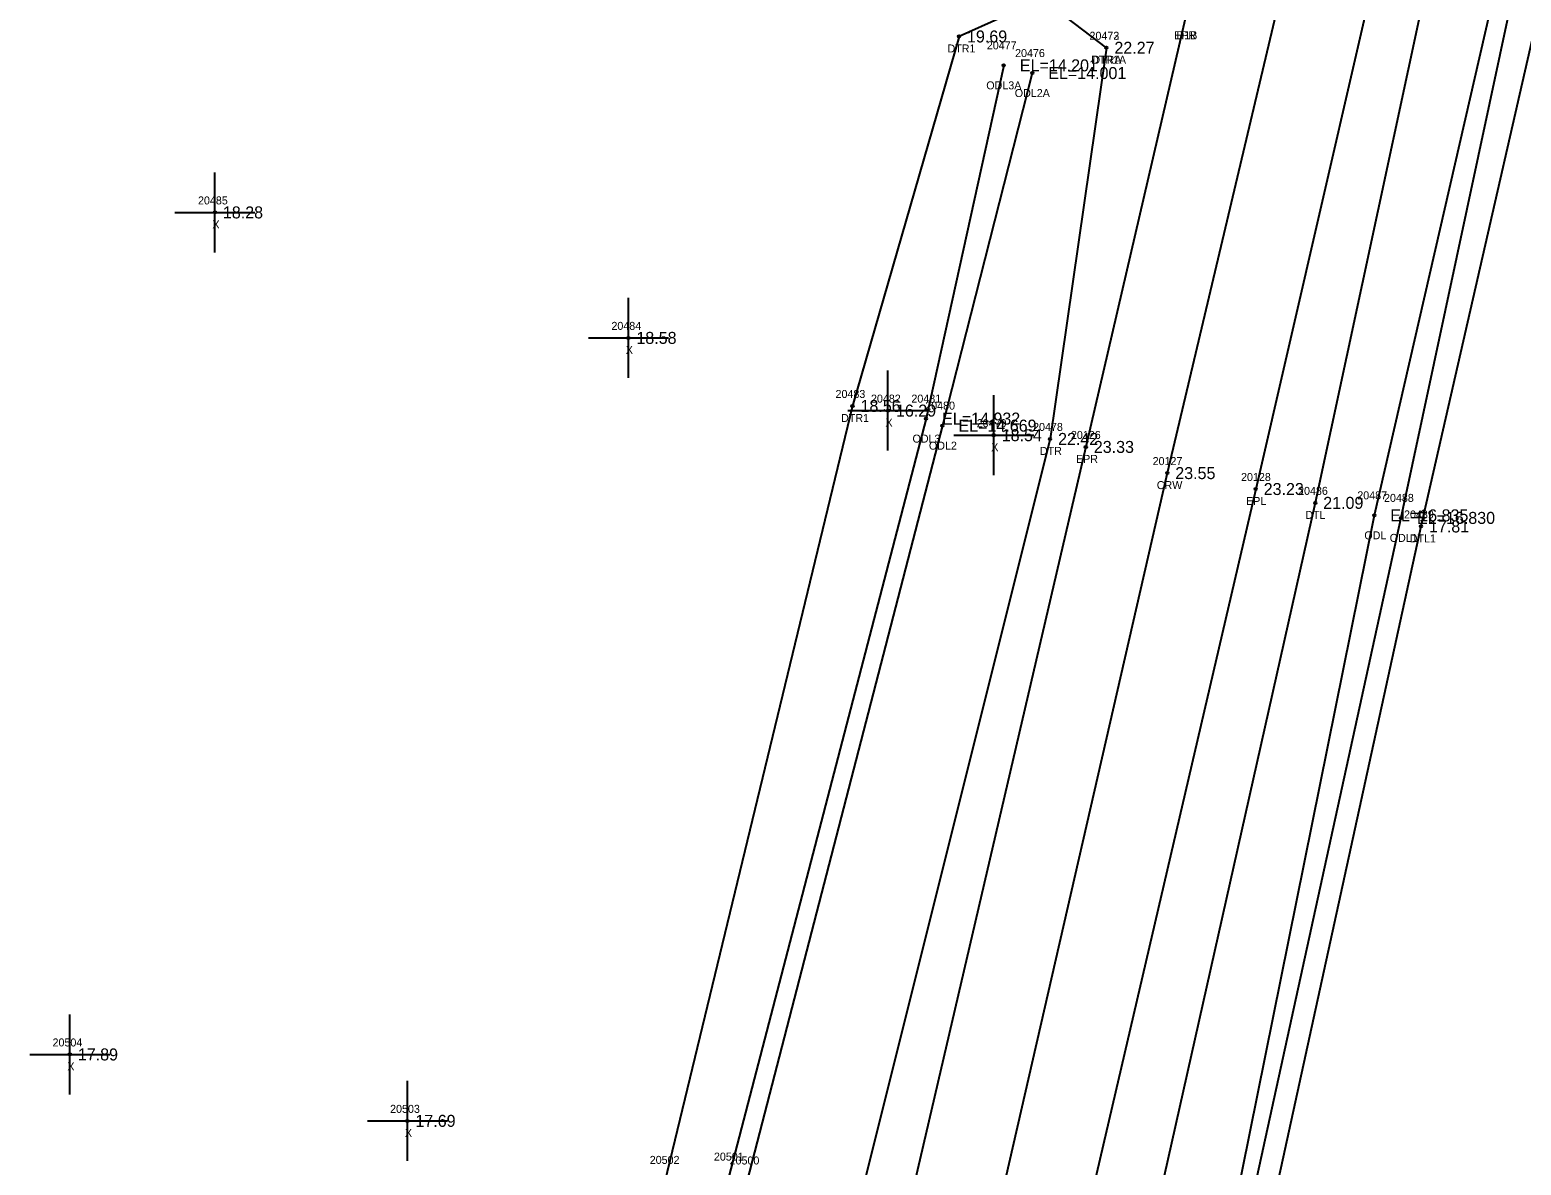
# Model space of a CAD drawing. Extents: x 2655177 to 2656219, y 761780 to 764748.
# Drawn here: x 2655627.1 to 2655813.5, y 763397.1 to 763539 of the extents above; entities that cross this region are included whole.
import ezdxf

# ---------------------------------------------------------------- set-up
doc = ezdxf.new("R2010")
doc.units = 0
for name, color, linetype in [('RD_DTM_BkLn1', 7, 'Continuous'), ('RD_EX_Driveway_txCode', 7, 'Continuous'), ('RD_EX_H2O', 7, 'Continuous'), ('RD_EX_H2O_txCode', 7, 'Continuous'), ('RD_EX_Misc', 7, 'Continuous'), ('RD_EX_Misc_txCode', 7, 'Continuous'), ('RD_EX_Road', 7, 'Continuous'), ('RD_EX_Road_txCode', 7, 'Continuous'), ('RD_EX_TX_H2O_ELEV', 7, 'Continuous'), ('RD_EX_TX_Misc_ELEV', 7, 'Continuous'), ('RD_EX_TX_Road_ELEV', 7, 'Continuous'), ('RD_HC_Survey_ELEV', 7, 'Continuous'), ('RD_HC_Survey_txCode', 7, 'Continuous'), ('RD_SMD_Locator', 7, 'Continuous')]:
    doc.layers.add(name, color=color, linetype=linetype)

msp = doc.modelspace()

# ---------------------------------------------------------------- linework, layer by layer
at = {"layer": 'RD_DTM_BkLn1'}
msp.add_lwpolyline([(2656052.36, 764720.46), (2656029.22, 764619.66), (2656007.41, 764523.97), (2655985.61, 764427.64), (2655963.53, 764330.64), (2655941.2, 764233.56), (2655920.06, 764141.06), (2655898.52, 764047.86), (2655877.71, 763954.88), (2655855.89, 763859.81), (2655834.07, 763763.97), (2655811.81, 763666.79), (2655790.48, 763573.22), (2655769.27, 763483.63), (2655747.64, 763389.32), (2655725.4, 763293.96), (2655721.51, 763275.9)], dxfattribs=at)
at = {"layer": 'RD_EX_H2O'}
for points in [[(2655866.2, 763781.92), (2655858.43, 763782.12), (2655853.29, 763757.63), (2655831.21, 763662.14), (2655807.21, 763570.59), (2655787.76, 763479.91), (2655766.41, 763384.86), (2655751.38, 763287.62), (2655745.55, 763261.6)], [(2655866.2, 763781.92), (2655866.81, 763773.88), (2655862.68, 763756.12), (2655841.51, 763659.39), (2655821.68, 763567.67), (2655800.98, 763476.96), (2655780.09, 763381.34), (2655766.41, 763289.68), (2655763.83, 763255.61)], [(2655859.17, 763772.66), (2655856.61, 763756.77), (2655834.86, 763661.01), (2655815.86, 763568.74), (2655795.14, 763478.35), (2655775.69, 763381.88), (2655758.88, 763290.93), (2655758.58, 763269.84), (2655756.39, 763249.8)], [(2655862.03, 763772.5), (2655859.51, 763756.17), (2655837.49, 763660.31), (2655817.79, 763568.47), (2655798.48, 763478.03), (2655777.42, 763381.75), (2655761.98, 763290.17), (2655758.58, 763269.84)], [(2655761.66, 763536.79), (2655753.68, 763542.9), (2655743.24, 763538.2), (2655729.93, 763492.02), (2655706.75, 763396.29), (2655684.97, 763303.64), (2655679.52, 763275.1)], [(2655761.66, 763536.79), (2655754.62, 763487.9), (2655730.78, 763392.48), (2655710.33, 763297.53), (2655707.49, 763283.28), (2655700.44, 763271.88)], [(2655748.84, 763534.59), (2655739.13, 763490.44), (2655714.48, 763395.7), (2655693.36, 763300.15), (2655683.42, 763267.23)], [(2655752.39, 763533.63), (2655741.17, 763489.56), (2655716.77, 763395.22), (2655694.81, 763299.79), (2655684.92, 763267.82)]]:
    msp.add_lwpolyline(points, dxfattribs=at)
at = {"layer": 'RD_EX_Misc'}
for p, q in [((2655650.24, 763511.21), (2655650.24, 763521.21)), ((2655645.24, 763516.21), (2655655.24, 763516.21)), ((2655701.92, 763495.53), (2655701.92, 763505.53)), ((2655696.92, 763500.53), (2655706.92, 763500.53)), ((2655734.36, 763486.44), (2655734.36, 763496.44)), ((2655747.58, 763483.37), (2655747.58, 763493.37)), ((2655729.36, 763491.44), (2655739.36, 763491.44)), ((2655742.58, 763488.37), (2655752.58, 763488.37)), ((2655632.11, 763405.97), (2655632.11, 763415.97)), ((2655627.11, 763410.97), (2655637.11, 763410.97)), ((2655674.3, 763397.67), (2655674.3, 763407.67)), ((2655669.3, 763402.67), (2655679.3, 763402.67))]:
    msp.add_line(p, q, dxfattribs=at)
at = {"layer": 'RD_EX_Road'}
for points in [[(2656041.72, 764723.31), (2656018.5, 764622.03), (2656002.75, 764552.49), (2655997.43, 764530.02), (2655974.74, 764429.64), (2655952.97, 764333.57), (2655930.52, 764235.7), (2655909.18, 764142.93), (2655887.93, 764050.57), (2655866.91, 763957.26), (2655846.82, 763869.53), (2655845.21, 763862.22), (2655839.99, 763839.71), (2655823.38, 763766.66), (2655801.33, 763669.93), (2655780.03, 763576.53), (2655774.26, 763551.85), (2655771.37, 763539.86), (2655759.09, 763486.9), (2655736.94, 763391.72), (2655715.19, 763296.77), (2655711.35, 763278.45)], [(2655930.84, 764138.62), (2655926.81, 764121.01), (2655909.26, 764045.26), (2655908.15, 764039.87), (2655902.08, 764013.51), (2655888.19, 763952.26), (2655880.73, 763919.6), (2655875, 763893.73), (2655866.73, 763857), (2655852.89, 763796.34), (2655850.73, 763786.52), (2655844.88, 763760.97), (2655822.62, 763664.7), (2655801.12, 763571.82), (2655780.32, 763481.64), (2655758.16, 763386.38), (2655736.73, 763291.27), (2655733.33, 763273.46)]]:
    msp.add_lwpolyline(points, dxfattribs=at)
at = {"layer": 'RD_SMD_Locator'}
for centre in [(2655743.24, 763538.2), (2655761.66, 763536.79), (2655761.66, 763536.79), (2655748.84, 763534.59), (2655752.39, 763533.63), (2655650.24, 763516.21), (2655701.92, 763500.53), (2655729.93, 763492.02), (2655734.36, 763491.44), (2655739.13, 763490.44), (2655741.17, 763489.56), (2655747.58, 763488.37), (2655754.62, 763487.9), (2655759.09, 763486.9), (2655769.27, 763483.63), (2655780.32, 763481.64), (2655787.76, 763479.91), (2655795.14, 763478.35), (2655798.48, 763478.03), (2655800.98, 763476.96), (2655632.11, 763410.97), (2655674.3, 763402.67)]:
    msp.add_circle(centre, 0.15, dxfattribs=at)

# ---------------------------------------------------------------- texts
at = {"layer": 'RD_EX_Driveway_txCode'}
msp.add_text('D1B', height=1, dxfattribs=at).set_placement((2655770.43, 763537.86))
at = {"layer": 'RD_EX_H2O_txCode'}
for s, p in [('DTR1', (2655741.8, 763536.2)), ('20477', (2655746.72, 763536.59)), ('20472', (2655759.55, 763537.79)), ('20473', (2655759.55, 763537.79)), ('20476', (2655750.25, 763535.63)), ('DTR1A', (2655759.74, 763534.79)), ('DTRA', (2655759.91, 763534.79)), ('ODL3A', (2655746.65, 763531.59)), ('ODL2A', (2655750.21, 763530.63)), ('20483', (2655727.81, 763493.02)), ('20481', (2655737.29, 763492.44)), ('20480', (2655739.02, 763491.56)), ('DTR1', (2655728.5, 763490.02)), ('20478', (2655752.5, 763488.9)), ('ODL3', (2655737.43, 763487.44)), ('ODL2', (2655739.48, 763486.56)), ('DTR', (2655753.35, 763485.9)), ('20486', (2655785.62, 763480.91)), ('20487', (2655793.02, 763480.35)), ('20488', (2655796.36, 763480.03)), ('DTL', (2655786.52, 763477.91)), ('20489', (2655798.86, 763477.96)), ('ODL', (2655793.9, 763475.35)), ('ODL1', (2655797.07, 763475.03)), ('DTL1', (2655799.57, 763474.96)), ('20502', (2655704.59, 763397.29)), ('20501', (2655712.61, 763397.7)), ('20500', (2655714.57, 763397.22))]:
    msp.add_text(s, height=1, dxfattribs=at).set_placement(p)
at = {"layer": 'RD_EX_Misc_txCode'}
for s, p in [('20485', (2655648.13, 763517.21)), ('X', (2655649.93, 763514.21)), ('20484', (2655699.8, 763501.53)), ('X', (2655701.6, 763498.53)), ('20482', (2655732.24, 763492.44)), ('X', (2655734.05, 763489.44)), ('20479', (2655745.46, 763489.37)), ('X', (2655747.27, 763486.37)), ('20504', (2655629.95, 763411.97)), ('X', (2655631.8, 763408.97)), ('20503', (2655672.14, 763403.67)), ('X', (2655673.99, 763400.67))]:
    msp.add_text(s, height=1, dxfattribs=at).set_placement(p)
at = {"layer": 'RD_EX_Road_txCode'}
for s, p in [('EPR', (2655770.14, 763537.86)), ('20126', (2655757.23, 763487.9)), ('EPR', (2655757.86, 763484.9)), ('20128', (2655778.49, 763482.64)), ('EPL', (2655779.12, 763479.64))]:
    msp.add_text(s, height=1, dxfattribs=at).set_placement(p)
at = {"layer": 'RD_EX_TX_H2O_ELEV'}
for s, p in [('19.69', (2655744.24, 763537.45)), ('22.27', (2655762.66, 763536.04)), ('22.27', (2655762.66, 763536.04)), ('EL=14.201', (2655750.84, 763533.84)), ('EL=14.001', (2655754.39, 763532.88)), ('18.56', (2655730.93, 763491.27)), ('EL=14.932', (2655741.13, 763489.69)), ('EL=14.669', (2655743.17, 763488.81)), ('22.42', (2655755.62, 763487.15)), ('21.09', (2655788.76, 763479.16)), ('EL=16.835', (2655797.14, 763477.6)), ('EL=16.830', (2655800.48, 763477.28)), ('17.81', (2655801.98, 763476.21))]:
    msp.add_text(s, height=1.5, dxfattribs=at).set_placement(p)
at = {"layer": 'RD_EX_TX_Misc_ELEV'}
for s, p in [('18.28', (2655651.24, 763515.46)), ('18.58', (2655702.92, 763499.78)), ('16.29', (2655735.36, 763490.69)), ('18.54', (2655748.58, 763487.62)), ('17.89', (2655633.11, 763410.22)), ('17.69', (2655675.3, 763401.92))]:
    msp.add_text(s, height=1.5, dxfattribs=at).set_placement(p)
at = {"layer": 'RD_EX_TX_Road_ELEV'}
for s, p in [('23.33', (2655760.09, 763486.15)), ('23.23', (2655781.32, 763480.89))]:
    msp.add_text(s, height=1.5, dxfattribs=at).set_placement(p)
at = {"layer": 'RD_HC_Survey_ELEV'}
msp.add_text('23.55', height=1.5, dxfattribs=at).set_placement((2655770.27, 763482.88))
at = {"layer": 'RD_HC_Survey_txCode'}
for s, p in [('20127', (2655767.44, 763484.63)), ('CRW', (2655767.96, 763481.63))]:
    msp.add_text(s, height=1, dxfattribs=at).set_placement(p)

doc.saveas('drawing.dxf')
